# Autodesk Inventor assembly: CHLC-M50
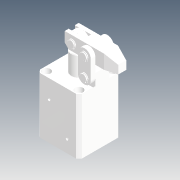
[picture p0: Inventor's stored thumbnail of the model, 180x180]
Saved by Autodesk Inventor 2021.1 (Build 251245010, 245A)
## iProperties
Company: Microsoft
Created: 2019-11
Part Number: CHLC-M50
Description: STEP AP214
Document SubType Name: Assembly
Designer: user
Title: CHLC-M50.STEP
Author: Windows
Revision Number: ÈÎºÎ
Sending System: SolidWorks 2015
Preprocessor: SwSTEP 2.0
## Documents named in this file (9)
- D:\Vault_2016\Projekty\Clamptek\Hydraulic\CHLC\CHLC-50\Inventor\CHLC-M50\CHLC-M50.iam
- D:\Vault_2016\Projekty\Clamptek\Hydraulic\CHLC\CHLC-50\Inventor\CHLC-M50\CHLC-M50-05.ipt
- D:\Vault_2016\Projekty\Clamptek\Hydraulic\CHLC\CHLC-50\Inventor\CHLC-M50\CHLC-50-09.ipt
- D:\Vault_2016\Projekty\Clamptek\Hydraulic\CHLC\CHLC-50\Inventor\CHLC-M50\CHLC-50-01.ipt
- D:\Vault_2016\Projekty\Clamptek\Hydraulic\CHLC\CHLC-50\Inventor\CHLC-M50\CHLC-50-03.ipt
- D:\Vault_2016\Projekty\Clamptek\Hydraulic\CHLC\CHLC-50\Inventor\CHLC-M50\CHLC-50-02.ipt
- D:\Vault_2016\Projekty\Clamptek\Hydraulic\CHLC\CHLC-50\Inventor\CHLC-M50\CHLC-50-04.ipt
- D:\Vault_2016\Projekty\Clamptek\Hydraulic\CHLC\CHLC-50\Inventor\CHLC-M50\CHLC-50-06.ipt
- D:\Vault_2016\Projekty\Clamptek\Hydraulic\CHLC\CHLC-50\Inventor\CHLC-M50\M6LS.ipt
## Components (16 placed, 16 different names)
1. CHLC-M50-05_1
2. CHLC-50-09_2
3. CHLC-50-01_3
4. CHLC-50-03_4
5. CHLC-50-03_5
6. CHLC-50-02_6
7. CHLC-50-04_7
8. CHLC-50-04_8
9. CHLC-50-06_9
10. CHLC-50-06_10
11. CHLC-50-06_11
12. CHLC-50-06_12
13. CHLC-50-06_13
14. CHLC-50-06_14
15. M6LS_15
16. M6LS_16
